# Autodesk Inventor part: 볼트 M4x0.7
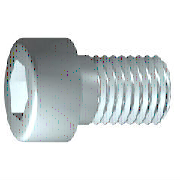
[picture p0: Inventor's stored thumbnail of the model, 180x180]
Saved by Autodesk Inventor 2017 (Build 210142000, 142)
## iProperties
IsCustomPart: 0
Created: 2015-12
Part Number: 볼트 M4x0.7
Material: 강철, 연강
Description: 6각머리 태핑 나사
Document SubType Name: Modeling
Standard: KS B 1003
Designer: mdu
Standards Organization: KS
Language: ko-KR
Size Designation: M 4 x 12
Categories: <MemberInstance><Categories><Category DisplayName="조임쇠" InternalName="e4da775c-781d-43d5-af7c-5136215cf5a6" Mnemonic="FSTN"><Category DisplayName="볼트" InternalN
Density: 7.86 g/cm^3
Mass: 2.23465 g
Surface Area: 3.30853 cm^2
Volume: 0.284306 cm^3
Appearance: 강철
Author: mdu
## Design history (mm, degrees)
sketch "스케치1"
  geometry: L1 (-1, 0)-(12, 0); L2 (12, 0)-(12, 2); L3 (12, 2)-(1.75, 2); L4 (1.75, 2)-(1.32, 2); L5 (1.32, 2)-(0, 2); L6 (0, 2)-(0, 3.5); L7 (0, 3.5)-(-4, 3.5); L8 (-4, 3.5)-(-4, 1.732); L9 (-4, 1.732)-(-2, 1.732); L10 (-2, 1.732)-(-1, 0); L11 (-7.2, 0)-(15.2, 0) reference; L12 (0, -0.7)-(0, 4.2) reference; L13 (1.75, 2)-(0, 2)
  constraints: 22 end point, 6 parallel, 2 collinear, 2 perpendicular, 1 horizontal, 1 point on line
  dimensions: "d1" = 10.25 distance from line of L3.end L2 (= GEL); "d2" = 0.42952 distance of L4.end L3.end (computed from GAL); "d3" = 4 distance between parallel lines of L8 L6 (= KOH); "d4" = 2 distance of L8.end L9.end (= INTI); "d5" = 60 deg angle of L10 L1; "d6" = 4 diameter of L3 L1 (= GD); "d7" = 4 diameter of L5 L1 (= BDM); "d8" = 3.4641 diameter of L9 L1 (= 1.1547 x SW); "d9" = 7 diameter of L7 L1 (= KOD); "d26" = 12 distance between parallel lines of L12 L2 (= NLG)
revolve "본체" sketch "스케치1" stored, may be unused: angle "d10" = 90 deg
sketch "스케치2"
  geometry: L1 (0, -4.9)-(0, 4.9) reference; L2 (-4.9, 0)-(4.9, 0) reference; L3 (1.732, 0)-(0.866, -1.5); L4 (0.866, -1.5)-(-0.866, -1.5); L5 (-0.866, -1.5)-(-1.732, 0); L6 (-1.732, 0)-(-0.866, 1.5); L7 (-0.866, 1.5)-(0.866, 1.5); L8 (0.866, 1.5)-(1.732, 0); 2 further points
  constraints: 12 end point, 1 coincident, 1 horizontal alignment, 1 point on line, 12 other
extrude "슬롯" join sketch "스케치2" stored distance "d11" = 10; taper "d12" = 0 deg
workplane "Work Plane1"
fillet "Fillet2" dims "d30" = 0.1 (= R)
body "Solid1"
fillet "모깎기1" dims "d17" = 0.4 (= RR)
feature "스레드" dims "d13" = 10.25 (= GEL), "d14" = 0
chamfer "모따기1" distance "d15" = 0.42941 (= -0.5 x SPD + 0.5 x GD); stored, may be unused: second distance "d16" = 0.42941 (= GUL), angle "d27" = 45 deg
other parameters: "GD" = 4 (= NND) [user parameter; used in 2 equation terms], "NLG" = 12 [user parameter; used in 1 equation term], "GEL" = 10.25 [user parameter; used in 2 equation terms], "KOD" = 7 [user parameter; used in 1 equation term], "KOH" = 4 [user parameter; used in 1 equation term], "INTI" = 2 [user parameter; used in 1 equation term], "GAL" = 0.42941 (= 0.61345 x PTC) [user parameter; used in 1 equation term], "GUL" = 0.42941 (= 0.61345 x PTC) [user parameter; used in 1 equation term], "BDM" = 4 (= NND) [user parameter; used in 1 equation term], "SW" = 3 [user parameter; used in 2 equation terms], "RR" = 0.4 [user parameter; used in 1 equation term], "SPD" = 3.14117 (= NND - 1.2269 x PTC) [user parameter; used in 1 equation term], "d19" = 0, "d28" = 0, "d29" = 0, "R" = 0.1 [user parameter; used in 1 equation term], "PHH" = 0.2 [user parameter], "GD1" = 3.14117 (= THREADDIA - 1.2269 x PTC) [user parameter], "THREADDIA" = 4 [user parameter; used in 1 equation term], "FAWI" = 45 deg [user parameter], "TPU" = 14.28571 (computed from PTC) [user parameter], "PTC" = 0.7 [user parameter; used in 5 equation terms], "NND" = 4 [user parameter; used in 3 equation terms], "TOA" = 30 deg [user parameter], "E0" = 3.465 (= 1.155 x SW) [user parameter]
